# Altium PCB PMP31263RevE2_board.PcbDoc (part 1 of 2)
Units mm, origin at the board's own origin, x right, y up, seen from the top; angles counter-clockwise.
Board outline 111.13 x 148.59 mm, 4 copper layers (Top Layer, Layer 1, Layer 2, Bottom Layer), stack 0.603 mm thick; 138 components, 59 nets, 350 pads, 1544 vias.
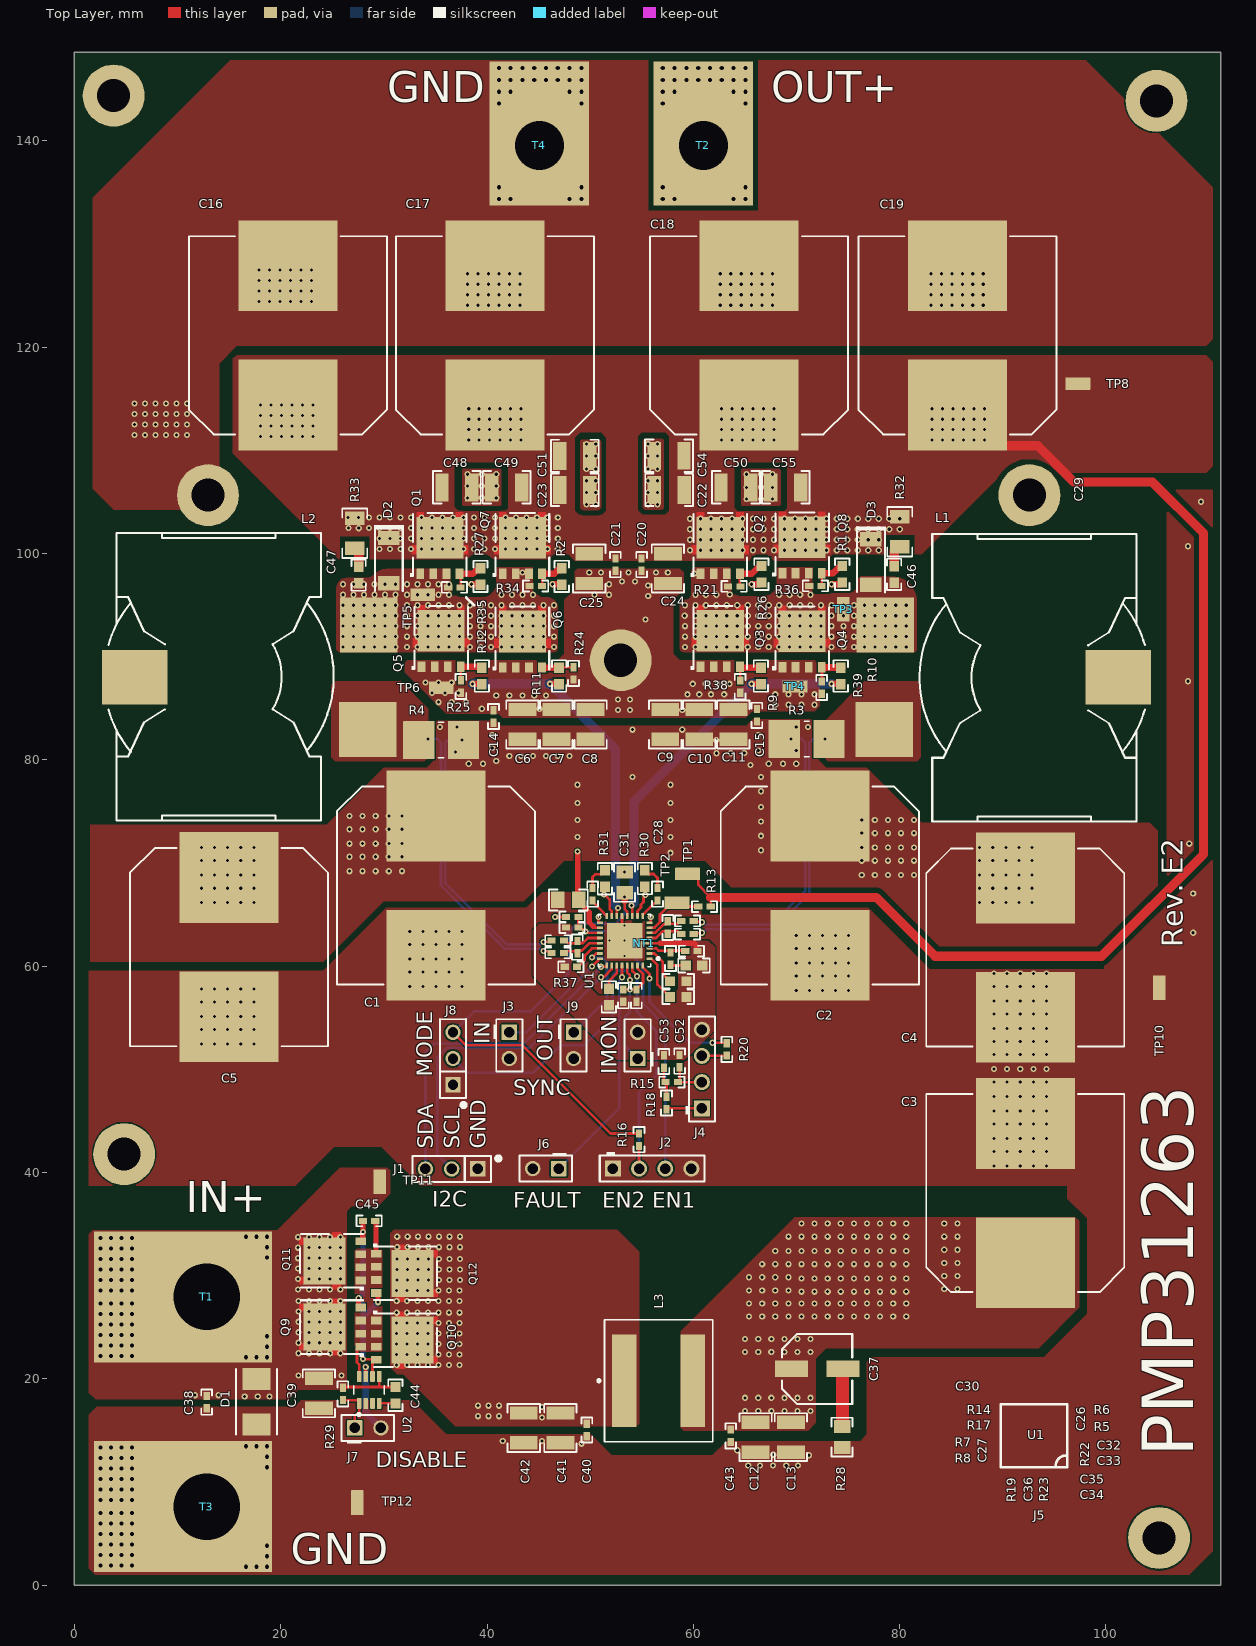
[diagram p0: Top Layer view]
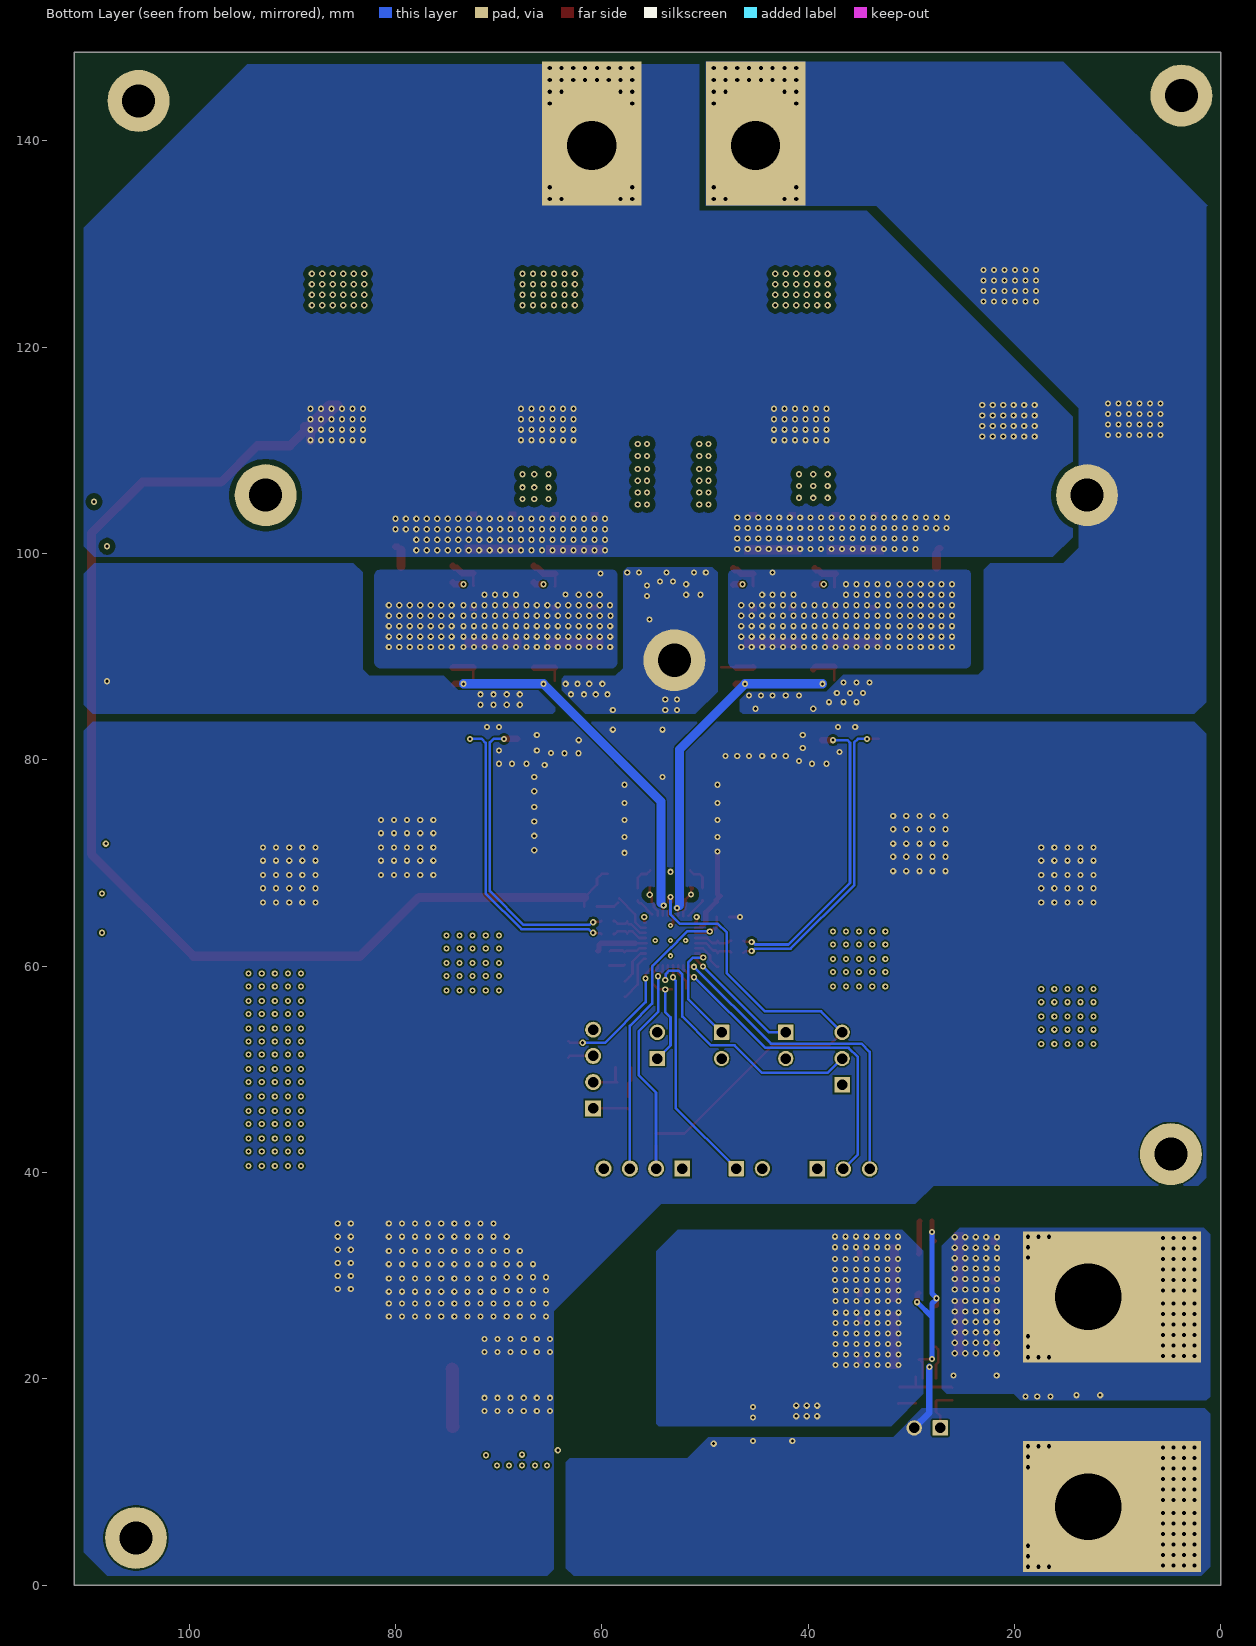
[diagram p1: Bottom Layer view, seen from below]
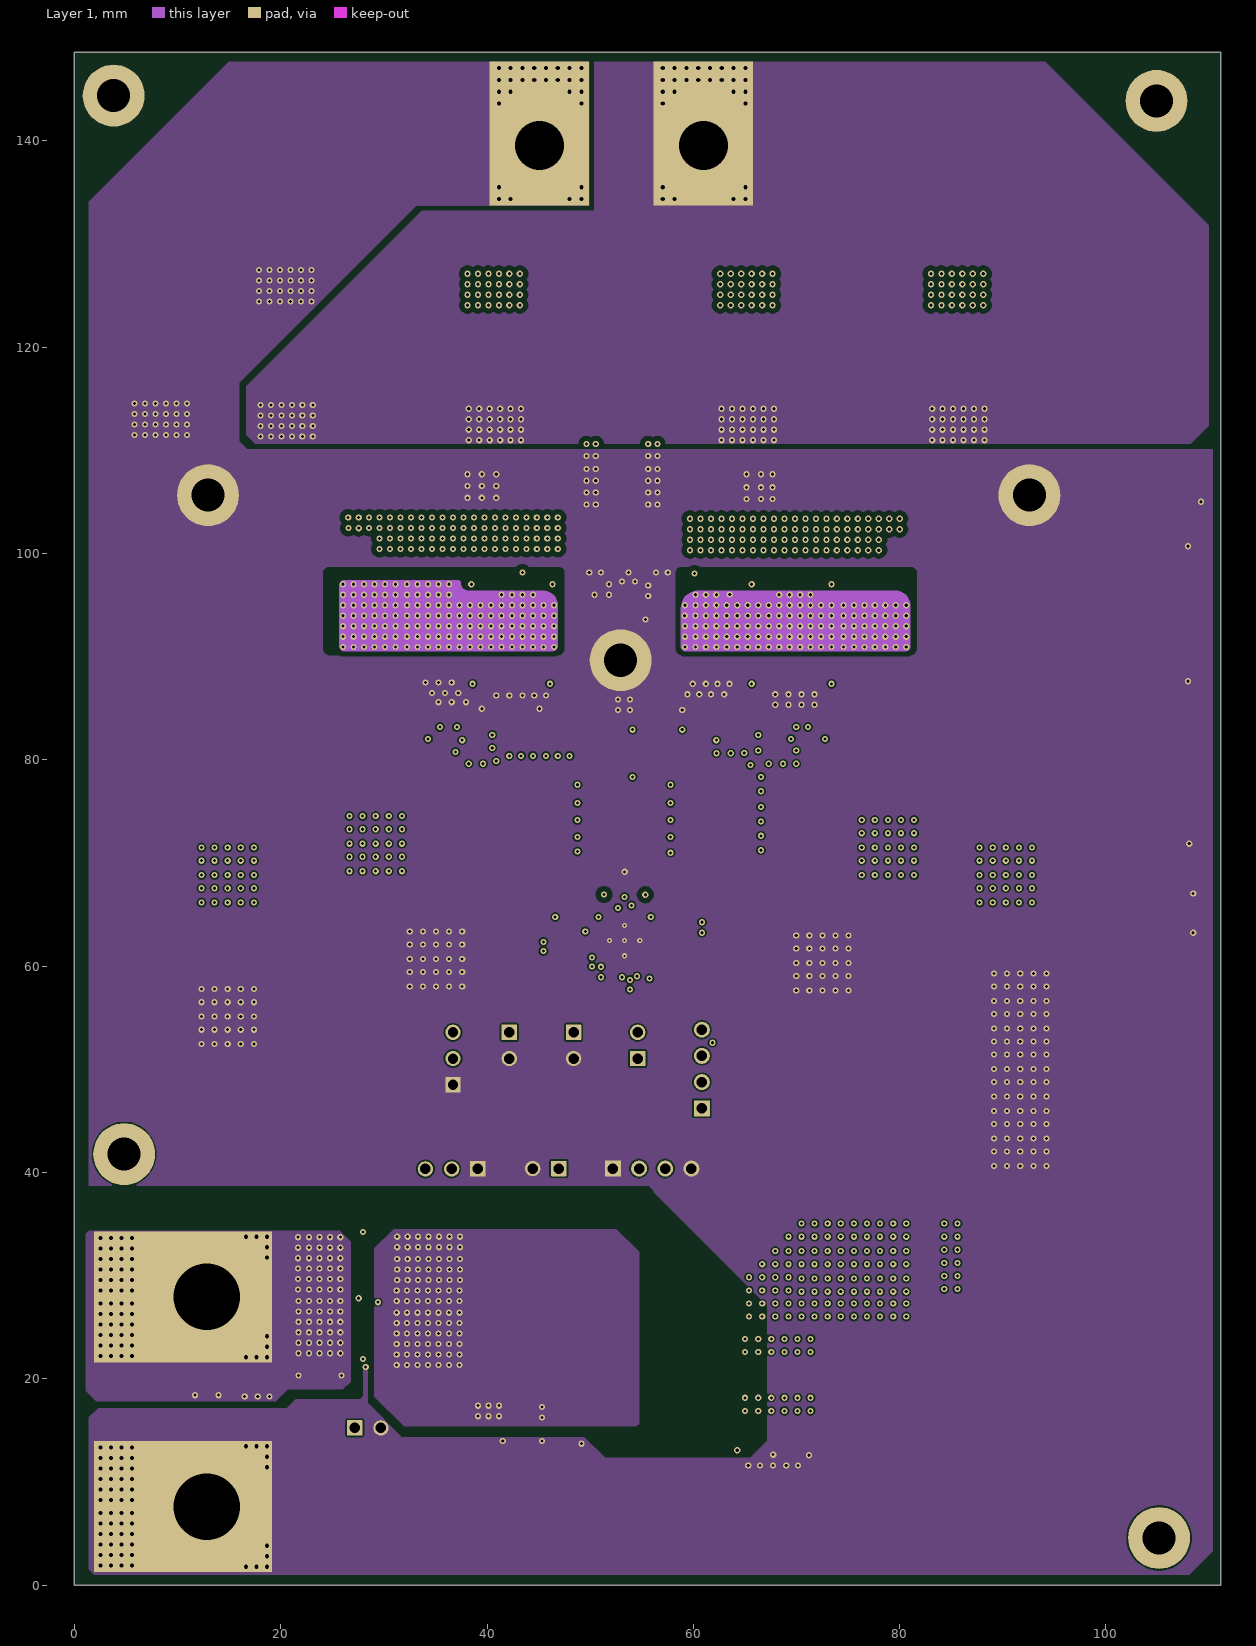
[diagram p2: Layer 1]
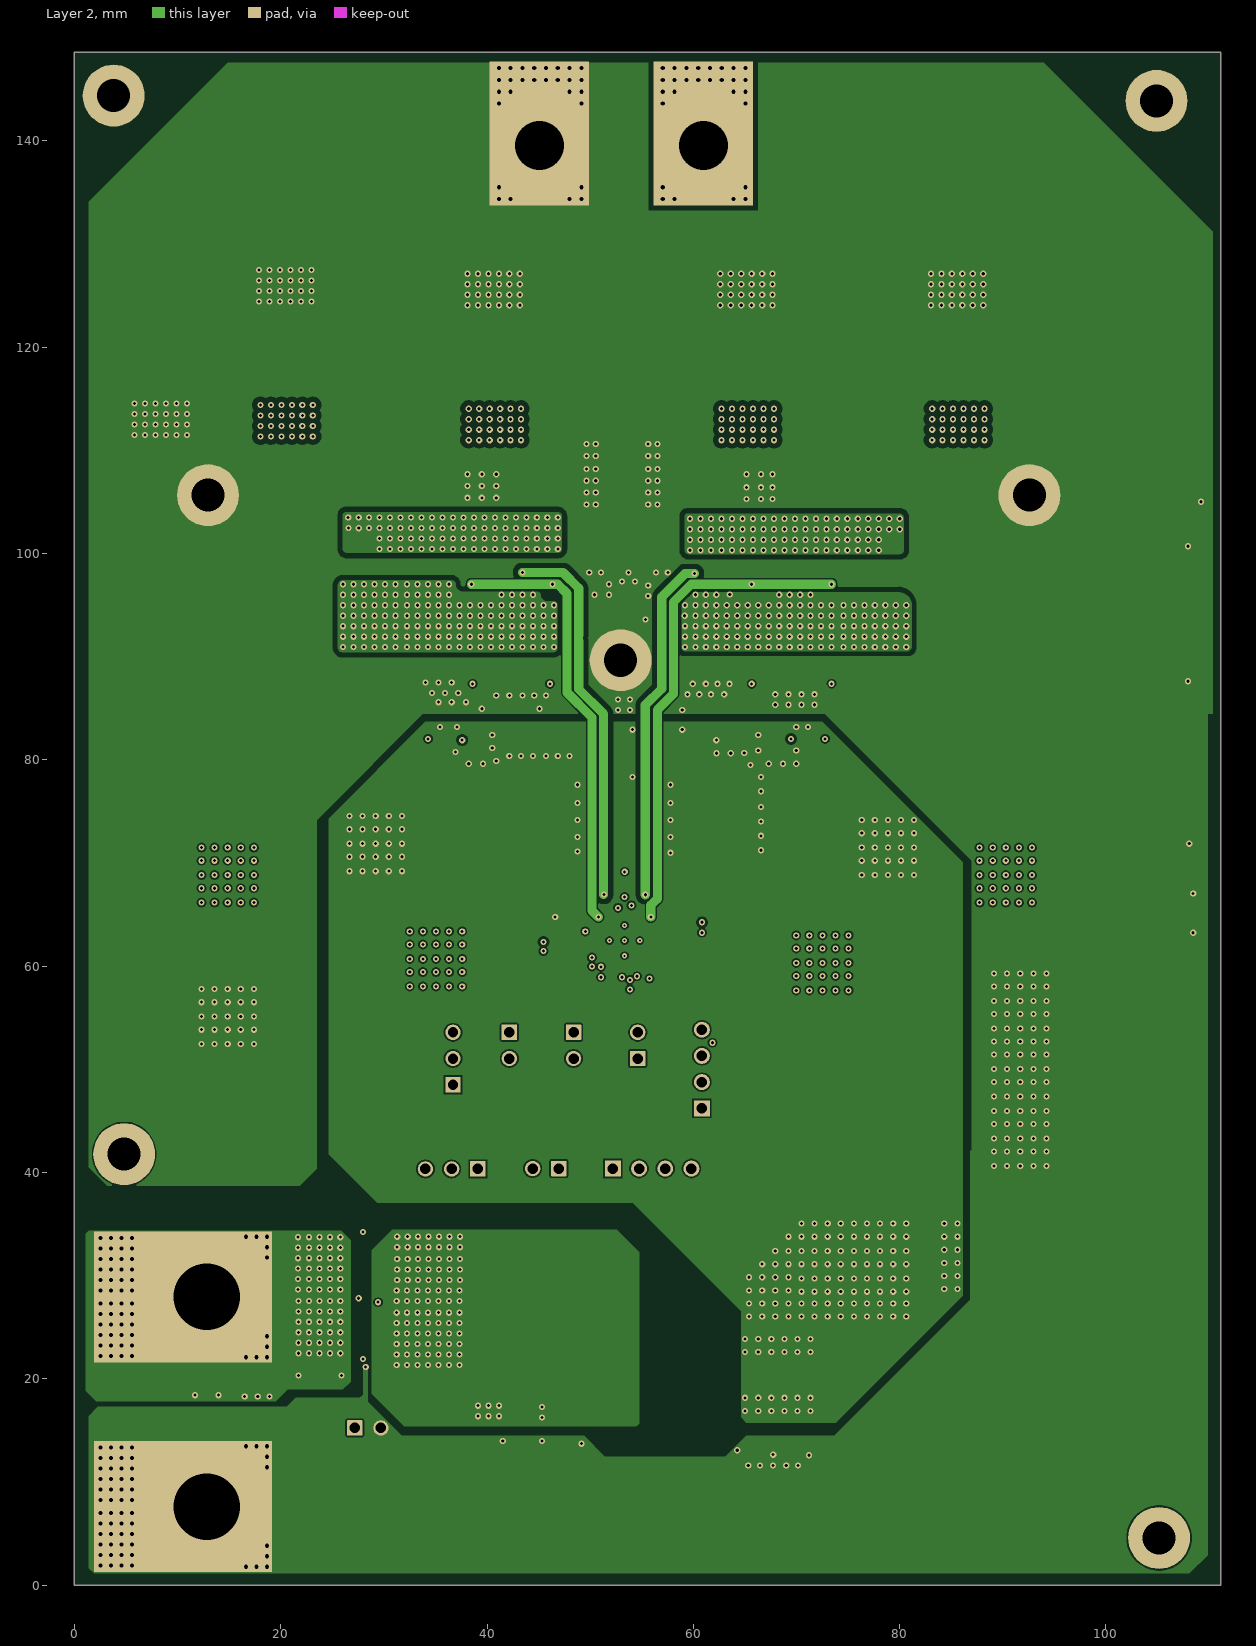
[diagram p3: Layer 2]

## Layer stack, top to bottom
Top Solder: solder mask 0.0102, Solder Resist, Dk 3.5
Top Layer: signal copper 0.0356
Dielectric 2: prepreg 0.0711, PP-006, Dk 4.1
Layer 1: signal copper 0.035
Dielectric 1: dielectric 0.32, FR-4, Dk 4.8
Layer 2: signal copper 0.035
Dielectric 3: prepreg 0.0711, PP-006, Dk 4.1
Bottom Layer: signal copper 0.0356
Bottom Solder: solder mask 0.0102, Solder Resist, Dk 3.5

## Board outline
0,0 0,148.59 111.125,148.59 111.125,0

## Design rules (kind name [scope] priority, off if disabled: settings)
Clearance SW [Not InNet('NetR1_1') And Not InNet('NetR2_2') vs InNet('SW1')  Or  InNet('SW2')  Or  InNet('Vboost')] p1: gap=0.508 ignorepadtopadclearanceinfootprint=FALSE
Clearance Clearance_1 [All] p2: gap=0.152 ignorepadtopadclearanceinfootprint=FALSE
HoleSize [All] p1: absolutevalues=TRUE maxlimit=8 minlimit=0.2 maxpercent=80.000 minpercent=20.000
MinimumAnnularRing [All] p1: minimumring=0.15
MinimumSolderMaskSliver [All] p1: minsoldermaskwidth=0.127
PolygonConnect [All] p1: connectstyle=Direct reliefconductorwidth=0.254 reliefentries=4 polygonreliefangle="90 Angle" airgapwidth=0.254
RoutingVias [All] p1: holewidth=0.3 width=0.6 viastyle="Through Hole" minholewidth=0.3 minwidth=0.6 maxholewidth=0.711 maxwidth=1.27
SolderMaskExpansion [All] p1: expansion=0.102 istentingtop=FALSE
Width [All] p1: maxlimit=1.27 minlimit=0.254 preferedwidth=0.254 minimp=50.000000 maximp=50.000000 favimp=50.000000
28 further rules are at their usual default settings.

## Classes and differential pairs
component class PMP31263RevE2_Input: C37 C38 C39 C40 C41 C42 C43 C44 C45 D1 J7 L3 Q9 Q10 Q11 Q12 R28 R29 T1 T3 TP11 TP12 U2
component class PMP31263: C1 C2 C3 C4 C5 C6 C7 C8 C9 C10 C11 C12 C13 C14 C15 C16 C17 C18 C19 C20 C21 C22 C23 C24 C25 C26 C27 C28 C29 C30 C31 C32 C33 C34 C35 C36 C46 C47 C48 C49 C50 C51 C52 C53 C54 C55 D2 D3 J1 J2 J3 J4 J5 J6 J8 J9 L1 L2 NT1 Q1 Q2 Q3 Q4 Q5 Q6 Q7 Q8 R1 R2 R3 R4 R5 R6 R7 R8 R9 R10 R11 R12 R13 R14 R15 R16 R17 R18 R19 R20 R21 R22 R23 R24 R25 R26 R27 R30 R31 R32 R33 R34 R35 R36 R37 R38 R39 T2 T4 TP1 TP2 TP3 TP4 TP5 TP6 TP8 TP10 U1

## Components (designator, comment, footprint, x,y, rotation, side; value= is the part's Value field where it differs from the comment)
C1 "EMVE500GTR102MMN0S" CAPSMT_62_MN0 35.052,67.818 r270 top value=1000uF
C2 "EMVE500GTR102MMN0S" CAPSMT_62_MN0 72.263,67.818 r270 top value=1000uF
C3 "EMVE500GTR102MMN0S" CAPSMT_62_MN0 92.182,38.013 r90 top value=1000uF
C4 "EMVE500GTR102MMN0S" CAPSMT_62_MN0 92.182,61.811 r270 top value=1000uF
C5 "EMVE500GTR102MMN0S" CAPSMT_62_MN0 14.986,61.849 r270 top value=1000uF
C6 "UMJ325KB7106KMHT" 1210_270 43.434,83.439 r90 top value=10uF
C7 "UMJ325KB7106KMHT" 1210_270 46.736,83.439 r90 top value=10uF
C8 "UMJ325KB7106KMHT" 1210_270 50.038,83.439 r90 top value=10uF
C9 "UMJ325KB7106KMHT" 1210_270 57.277,83.439 r90 top value=10uF
C10 "UMJ325KB7106KMHT" 1210_270 60.579,83.439 r90 top value=10uF
C11 "UMJ325KB7106KMHT" 1210_270 63.881,83.439 r90 top value=10uF
C12 "UMJ325KB7106KMHT" 1210_270 66.04,14.351 r270 top value=10uF
C13 "UMJ325KB7106KMHT" 1210_270 69.469,14.351 r270 top value=10uF
C14 "CGA2B3X7R1H104K050BB" 0402 40.631,84.203 r90 top value=0.1uF
C15 "CGA2B3X7R1H104K050BB" 0402 66.167,84.328 r90 top value=0.1uF
C16 "EMVE500GTR102MMN0S" CAPSMT_62_MN0 20.701,121.158 r90 top value=1000uF
C17 "EMVE500GTR102MMN0S" CAPSMT_62_MN0 40.767,121.158 r90 top value=1000uF
C18 "EMVE500GTR102MMN0S" CAPSMT_62_MN0 65.405,121.158 r90 top value=1000uF
C19 "EMVE500GTR102MMN0S" CAPSMT_62_MN0 85.598,121.158 r90 top value=1000uF
C20 "CGA2B3X7R1H104K050BB" 0402 54.991,98.933 r270 top value=0.1uF
C21 "CGA2B3X7R1H104K050BB" 0402 52.451,98.933 r270 top value=0.1uF
C22 "UMJ325KB7106KMHT" 1210_270 57.658,106.172 r180 top value=10uF
C23 "UMJ325KB7106KMHT" 1210_270 48.514,106.172 r0 top value=10uF
C24 "UMJ325KB7106KMHT" 1210_270 57.531,98.552 r270 top value=10uF
C25 "UMJ325KB7106KMHT" 1210_270 49.911,98.552 r270 top value=10uF
C26 "CGA2B2C0G1H101J050BA" 0402 57.531,63.754 r270 top value=100pF
C27 "CGA2B2C0G1H101J050BA" 0402 48.768,61.849 r90 top value=100pF
C28 "CGA2B3X7R1H104K050BB" 0402 56.526,66.982 r270 top value=0.1uF
C29 "CGA2B3X7R1H104K050BB" 0402 50.231,66.982 r90 top value=0.1uF
C30 "CGA4J3X7R1H225K125AB" 0805_HV 47.879,66.421 r180 top value=2.2uF
C31 "CGA4J3X7R1C475K125AE" 0805_HV 53.333,68.137 r90 top value=4.7uF
C32 "GCM155R71H222KA37D" 0402 59.817,61.468 r0 top value=2200pF
C33 "CGA3E3X7R1H474K080AB" 0603 60.071,60.071 r0 top value=0.47uF
C34 "CGA3E3X7R1H334K080AB" 0603 58.547,57.023 r0 top value=0.33uF
C35 "CGA3E3X7R1H334K080AB" 0603 58.547,58.547 r0 top value=0.33uF
C36 "CGA2B2C0G1H101J050BA" 0402 53.213,57.15 r270 top value=100pF
C37 "EEEFT1H470AP" Panasonic_D 72.009,20.955 r0 top value=47uF
C38 "CGA2B3X7R1H104K050BB" 0402 12.827,17.745 r270 top value=0.1uF
C39 "GCM32ER71H475KA55L" 1210_270 23.698,18.592 r270 top value=4.7uF
C40 "CGA2B3X7R1H104K050BB" 0402 49.678,15.039 r270 top value=0.1uF
C41 "UMJ325KB7106KMHT" 1210_270 47.117,15.24 r270 top value=10uF
C42 "UMJ325KB7106KMHT" 1210_270 43.561,15.24 r270 top value=10uF
C43 "CGA2B3X7R1H104K050BB" 0402 63.627,14.478 r270 top value=0.1uF
C44 "CGA3E3X7R1H474K080AE" 0603 31.115,18.415 r90 top value=0.47uF
C45 "CGA2B3X7R1H104K050BB" 0402 28.575,35.306 r180 top value=0.1uF
C46 "CGA3E2X7R2A152K080AA" 0603 79.472,97.982 r270 top value=1500pF
C47 "CGA3E2X7R2A152K080AA" 0603 27.559,97.917 r270 top value=1500pF
C48 "UMJ325KB7106KMHT" 1210_270 37.084,106.426 r0 top value=10uF
C49 "UMJ325KB7106KMHT" 1210_270 41.91,106.426 r180 top value=10uF
C50 "UMJ325KB7106KMHT" 1210_270 64.135,106.426 r0 top value=10uF
C51 "UMJ325KB7106KMHT" 1210_270 48.514,109.474 r0 top value=10uF
C52 "CGA2B3X7R1H103K050BB" 0402 58.674,50.8 r90 top value=0.01uF
C53 "CGA2B3X7R1H103K050BB" 0402 57.15,50.765 r90 top value=0.01uF
C54 "UMJ325KB7106KMHT" 1210_270 57.648,109.484 r180 top value=10uF
C55 "UMJ325KB7106KMHT" 1210_270 68.961,106.426 r180 top value=10uF
D1 "SMBJ33CA-13-F" SMB-Bi 17.653,17.78 r90 top value=33V
D2 "PMEG6030EVPX" SOD-128 30.48,99.314 r270 top value=60V
D3 "PMEG6030EVPX" SOD-128 77.216,99.187 r270 top value=60V
J1 "PEC03SAAN" CONN_PEC03SAAN 36.572,40.346 r180 top
J2 "PBC04SAAN" Sullins_xxC04SAAN 56.007,40.386 r0 top
J3 "PEC02SAAN" CONN_PEC02SAAN 42.164,52.324 r270 top
J4 "PBC04SAAN" Sullins_xxC04SAAN 60.833,50.038 r90 top
J5 "PEC02SAAN" CONN_PEC02SAAN 54.61,52.324 r90 top
J6 "PEC02SAAN" CONN_PEC02SAAN 45.69,40.386 r180 top
J7 "PEC02SAAN" CONN_PEC02SAAN 28.448,15.24 r0 top
J8 "PEC03SAAN" CONN_PEC03SAAN 36.703,51.054 r90 top
J9 "PEC02SAAN" CONN_PEC02SAAN 48.387,52.324 r270 top
L1 "SER2915H-332KL" SER2915H 92.964,88.011 r0 top value=3.3uH
L2 "SER2915H-332KL" SER2915H 14.097,88.011 r180 top locked value=3.3uH
L3 "XAL1010-451MEB" FP-XAL1010-451MEB_SMD2-MFG 56.642,19.812 r0 top value=0.45uH
NT1 "Net-Tie" Net-Tie_10milWide_30milLong 55.262,62.238 r180 top net-tie
Q1 "NVMYS2D9N04CL" SO-8FL 35.433,100.838 r90 top value=60V
Q2 "NVMYS2D9N04CL" SO-8FL 62.611,100.839 r90 top value=60V
Q3 "NVMYS2D9N04CL" SO-8FL 62.611,91.821 r90 top value=60V
Q4 "NVMYS2D9N04CL" SO-8FL 70.548,91.78 r90 top value=60V
Q5 "NVMYS2D9N04CL" SO-8FL 35.56,91.821 r90 top value=60V
Q6 "NVMYS2D9N04CL" SO-8FL 43.434,91.758 r90 top value=60V
Q7 "NVMYS2D9N04CL" SO-8FL 43.434,100.838 r90 top value=60V
Q8 "NVMYS2D9N04CL" SO-8FL 70.548,100.892 r90 top value=60V
Q9 "NVMFWS0D5N04XM" SO-8FL 24.956,25.019 r180 top value=60V
Q10 "NVMFWS0D5N04XM" SO-8FL 32.068,23.749 r0 top value=60V
Q11 "NVMFWS0D5N04XM" SO-8FL 24.957,31.445 r180 top value=60V
Q12 "NVMFWS0D5N04XM" SO-8FL 32.069,30.226 r0 top value=60V
R1 "PMR03EZPJ000" 0603 74.435,98.005 r90 top value=0
R2 "PMR03EZPJ000" 0603 47.242,97.792 r270 top value=0
R3 "WSLP25121L500FEA" FP-WSLP25121L500FEA_2512-MFG 70.993,82.042 r180 top value=1.5m
R4 "WSLP25121L500FEA" FP-WSLP25121L500FEA_2512-MFG 35.56,81.915 r180 top value=1.5m
R5 "RK73Z1ETTP" 0402 59.436,63.119 r0 top value=0
R6 "RK73Z1ETTP" 0402 59.436,64.389 r0 top value=0
R7 "RK73Z1ETTP" 0402 46.863,62.484 r180 top value=0
R8 "RK73Z1ETTP" 0402 46.862,61.296 r180 top value=0
R9 "PMR03EZPJ000" 0603 66.548,88.138 r90 top value=0
R10 "PMR03EZPJ000" 0603 74.295,88.138 r90 top value=0
R11 "PMR03EZPJ000" 0603 46.99,88.138 r90 top value=0
R12 "PMR03EZPJ000" 0603 39.497,88.138 r90 top value=0
R13 "CRCW040249R9FKED" 0402 61.087,65.786 r0 top value=49.9
R14 "RMCF0402FT100K" 0402 48.26,64.77 r180 top value=100k
R15 "CRCW04021K54FKED" 0402 57.912,48.768 r0 top value=1.54k
R16 "RMCF0402FT100K" 0402 54.737,43.18 r90 top value=100k
R17 "CRCW040214K0FKED" 0402 48.26,63.754 r0 top value=14.0k
R18 "CRCW04021K54FKED" 0402 57.404,46.736 r270 top value=1.54k
R19 "PMR03EZPJ000" 0603 51.816,57.023 r90 top value=0
R20 "CRCW0402100KFKED" 0402 63.246,51.943 r270 top value=100k
R21 "RMCF0402FT100K" 0402 63.964,96.825 r0 top value=100k
R22 "RMCF0402FT10K0" 0402 57.785,60.741 r90 top value=10.0k
R23 "CRCW040220K0FKED" 0402 54.483,57.15 r90 top value=20.0k
R24 "RMCF0402FT100K" 0402 48.387,88.392 r90 top value=100k
R25 "RMCF0402FT100K" 0402 37.465,87.122 r90 top value=100k
R26 "PMR03EZPJ000" 0603 66.603,98.005 r90 top value=0
R27 "PMR03EZPJ000" 0603 39.37,97.79 r270 top value=0
R28 "ERJ-6GEY0R00V" 0805_HV 74.422,14.351 r90 top value=0
R29 "RMCF0402FT100K" 0402 26.035,18.542 r90 top value=100k
R30 "PMR03EZPJ000" 0603 55.298,68.509 r270 top value=0
R31 "PMR03EZPJ000" 0603 51.435,68.491 r90 top value=0
R32 "CRCW1206102RFKEA" 1206 80.01,102.108 r90 top value=102
R33 "CRCW1206102RFKEA" 1206 27.178,101.981 r90 top value=102
R34 "RMCF0402FT100K" 0402 44.723,96.857 r0 top value=100k
R35 "RMCF0402FT100K" 0402 36.838,96.725 r0 top value=100k
R36 "RMCF0402FT100K" 0402 71.831,96.869 r0 top value=100k
R37 "RMCF0402FT100K" 0402 48.133,59.944 r180 top value=100k
R38 "RMCF0402FT100K" 0402 64.543,87.1 r90 top value=100k
R39 "RMCF0402FT100K" 0402 72.445,87.014 r270 top value=100k
T1 "CB70-14-CY" CB70-14-CY 12.827,27.94 r0 top
T2 "CB35-36-CY" CB35-36-CY 60.983,139.573 r270 top
T3 "CB70-14-CY" CB70-14-CY 12.827,7.622 r0 top
T4 "CB35-36-CY" CB35-36-CY 45.085,139.573 r270 top
TP1 "RCU-0C" TE_RCU 59.436,68.961 r0 top
TP2 "RCU-0C" TE_RCU 58.42,66.167 r0 top
TP3 "RCU-0C" TE_RCU 74.549,94.615 r90 top
TP4 "RCU-0C" TE_RCU 69.85,87.122 r180 top
TP5 "RCU-0C" TE_RCU 33.782,96.012 r180 top
TP6 "RCU-0C" TE_RCU 35.56,86.995 r180 top
TP8 "RCU-0C" TE_RCU 97.282,116.459 r180 top
TP10 "RCU-0C" TE_RCU 105.156,57.912 r90 top
TP11 "RCU-0C" TE_RCU 29.591,39.116 r90 top
TP12 "RCU-0C" TE_RCU 27.432,8.001 r90 top
U1 "LM5125-Q1RHB" PCBComponent_1 53.34,62.484 r180 top
U2 "LM74502QDDFQ1" DDF0008A-MFG 28.575,18.923 r90 top

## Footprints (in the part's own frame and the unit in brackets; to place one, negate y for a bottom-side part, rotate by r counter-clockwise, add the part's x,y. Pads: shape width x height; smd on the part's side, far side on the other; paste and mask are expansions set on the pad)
0402 [mm] "0402 from SM-752 data"
  rect 0.8x0.6 smd: 1(-0.6,0) 2(0.6,0)
  silkscreen extent -1.22,-0.52 1.22,0.52, body extent -0.55,-0.3 0.55,0.3, height 0.6
0603 [mm] "0603 from SM-752 data"
  rect 1x0.95 smd: 1(-0.8,0) 2(0.8,0)
  silkscreen extent -1.52,-0.69 1.52,0.69, body extent -0.87,-0.47 0.87,0.47, height 1
0805_HV [mil] "0805 with 30mil clearance between pads"
  rect 50x63 smd: 1(-40,0) 2(40,0)
  silkscreen extent -74,-40 74,40, body extent -43,-29 43,29, height 57
1206 [mm] "1206 from SM-752 data"
  rect 1.3x1.85 smd: 1(-1.45,0) 2(1.45,0)
  silkscreen extent -2.4,-1.21 2.4,1.21, body extent -1.7,-0.9 1.7,0.9, height 1.35
1210_270 [mm] "1210"
  rect 1.3x2.7 smd: 1(-1.45,0) 2(1.45,0)
  silkscreen extent -2.32,-1.57 2.32,1.57, body extent -1.7,-1.35 1.7,1.35, height 2.7
CAPSMT_62_MN0 [mm] "18 x 21.5mm:  Chemi-Con MN0"
  rect 8.8x9.6 smd: 1(-6.75,0) 2(6.75,0)
  silkscreen extent -9.6,-9.6 9.6,9.6, body extent -9.6,-9.6 9.6,9.6, height 22
CB35-36-CY [mil] "Terminal 50A Lug"
  rect 550x380 hole 188 copper offset -45,0 paste-99999: 1(0,0)
  body extent -960,-189 230,191, height 614
CB70-14-CY [mil] "Terminal 90A Lug"
  rect 680x500 hole 254 copper offset -90,0 paste-99999: 1(0,0)
  body extent -1300,-260 250,260, height 714
CONN_PEC02SAAN [mm] "SULLINS"
  rrect7% 1.5x1.5 hole 1.016: 1(-1.27,0)
  round 1.5 hole 1.016: 2(1.27,0)
  silkscreen extent -2.54,-1.52 2.54,1.27, body extent -2.54,-1.27 2.54,1.27, height 8.38
CONN_PEC03SAAN [mm] "SULLINS"
  rect 1.5x1.5 hole 1.016: 1(-2.54,0)
  round 1.5 hole 1.016: 2(0,0) 3(2.54,0)
  silkscreen extent -4.72,-1.27 3.81,1.27, body extent -3.84,-1.3 3.84,1.3, height 8.38
DDF0008A-MFG [mm]
  rrect22% 1.05x0.45 smd paste+0 mask+0: 1(-1.3,0.975) 2(-1.3,0.325) 3(-1.3,-0.325) 4(-1.3,-0.975) 5(1.3,-0.975) 6(1.3,-0.325) 7(1.3,0.325) 8(1.3,0.975)
  silkscreen extent -2.5,-1.48 0.4,1.48, body extent -1.92,-1.73 1.92,1.73, height 0.25
FP-WSLP25121L500FEA_2512-MFG [mm]
  rrect3% 3.05x3.68 smd paste+0 mask+0: 1(-2.16,0) 2(2.16,0)
  silkscreen extent -0.26,-1.72 0.26,1.72, body extent -3.78,-1.94 3.78,1.94, height 0.25
FP-XAL1010-451MEB_SMD2-MFG [mm]
  rrect4% 2.38x9 smd paste+0 mask+0: 1(-3.325,0) 2(3.325,0)
  silkscreen extent -5.92,-5.9 5.25,5.9, body extent -5.35,-6 5.35,6, height 0.25
Net-Tie_10milWide_30milLong [mil] "10mil net tie, no solder mask opening, no solder paste"
  rect 30x10 smd paste-5 mask-5: 1(-15,0) 2(15,0)
Panasonic_D [mm] "SMD, 2-Leads, Dia 6.3mm"
  rect 3.2x1.6 smd: 1(-2.5,0) 2(2.5,0)
  silkscreen extent -3.4,-3.4 3.4,3.4, body extent -3.4,-3.4 3.4,3.4, height 6.11
PCBComponent_1 [mm]
  rrect40% 0.6x0.25 smd paste+0 mask+0: 1(-2.4,1.75) 2(-2.4,1.25) 3(-2.4,0.75) 4(-2.4,0.25) 5(-2.4,-0.25) 6(-2.4,-0.75) 7(-2.4,-1.25) 8(-2.4,-1.75) 17(2.4,-1.75) 18(2.4,-1.25) 19(2.4,-0.75) 20(2.4,-0.25) 21(2.4,0.25) 22(2.4,0.75) 23(2.4,1.25) 24(2.4,1.75)
  rrect40% 0.25x0.6 smd paste+0 mask+0: 9(-1.75,-2.4) 10(-1.25,-2.4) 11(-0.75,-2.4) 12(-0.25,-2.4) 13(0.25,-2.4) 14(0.75,-2.4) 15(1.25,-2.4) 16(1.75,-2.4) 25(1.75,2.4) 26(1.25,2.4) 27(0.75,2.4) 28(0.25,2.4) 29(-0.25,2.4) 30(-0.75,2.4) 31(-1.25,2.4) 32(-1.75,2.4)
  rrect3% 3.45x3.45 smd paste-1000 mask+0: 33(0,0)
  silkscreen extent -3.38,-2.55 2.55,2.55, body extent -2.5,-2.5 2.5,2.5, height 1
SER2915H [mm] "COILCRAFT"
  rect 5.59x5.33 smd: 1(-14.355,5.075) 2(-14.455,-5.075)
  rect 6.35x5.28 smd: 3(8.25,0)
  silkscreen extent -11.04,-14 10.81,13.9, body extent -16.7,-14.05 11.22,13.85, height 15.4
SMB-Bi [mm] "Molded Diode, 2-Leads, Body 5.4x3.6mm, IPC Medium Density, based on OnSemi component dimensions"
  rect 2.159x2.743 smd: 1(-2.21,0) 2(2.21,0)
  silkscreen extent -3.17,-1.99 3.17,1.99, body extent -2.65,-1.85 2.65,1.85, height 2.26
SO-8FL [mm] "ON SEMICONDUCTOR, DFN5 5x6, 1.27P, CASE 488AA"
  rect 1x0.75 smd: 1(-2.795,1.905) 2(-2.795,0.635) 3(-2.795,-0.635) 4(-2.795,-1.905)
  rect 4.055x4.56 smd: 5(0.698,0)
  Top Layer region: 0,-2.775 0,2.775 -0.905,2.775 -0.905,-2.775
  Top Layer region: 3.199,1.529 3.199,2.279 2.654,2.279 2.654,1.529
  Top Layer region: 3.199,-2.281 3.199,-1.531 2.649,-1.531 2.649,-2.281
  silkscreen extent -3.1,-2.6 3.1,2.9, body extent -3.17,-2.67 3.17,2.67, height 1.11
SOD-128 [mm] "SMD, 2-Leads, Body 4x2.7mm, Height 1.1mm"
  rect 1.4x2.1 smd paste-0.1: 1(-2.2,0) 2(2.2,0)
  silkscreen extent -3.45,-1.45 2.95,1.45, body extent -2.5,-1.35 2.5,1.35, height 1.11
Sullins_xxC04SAAN [mm] "Header, 2.54 mm, 4x1, TH"
  rect 1.55x1.55 hole 1.016: 1(-3.81,0)
  round 1.55 hole 1.016: 2(-1.27,0) 3(1.27,0) 4(3.81,0)
  silkscreen extent -5.08,-1.27 5.08,1.6, body extent -5.08,-1.27 5.08,1.27, height 8.38
TE_RCU [mm] "SMD, 1-Leads, Body 1.6x0.8mm"
  rrect8% 2.4x1.2 smd: 1(0,0)
  body extent -0.8,-0.45 0.8,0.45, height 1.15

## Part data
C1 C2 C3 C4 C5 C16 C17 C18 C19: library part CMP-0011290-3, "CAP, AL, 1000 uF, 50 V, +/- 20%, SMD", Cap_Case=MN0, Manufacturer=Chemi-Con, Tolerance_%=20%, Value1=Unknown, Value2=50V, ValueDisplayed=1000uF
C6 C7 C8 C9 C10 C11 C12 C13 C22 C23 C24 C25 C41 C42 C48 C49 C50 C51 C54 C55: library part CMP-0009257-2, "CAP, CERM, 10 uF, 50 V, +/- 10%, X7R, AEC-Q200 Grade 1, 1210", Cap_Case=1210, Manufacturer="Taiyo Yuden", Supplier Part Number 1=587-4279-1-ND, TempCo=X7R, Tolerance_%=10%, Value1=Unknown, Value2=50V, ValueDisplayed=10uF
C14 C15 C20 C21 C28 C29 C38 C40 C43 C45: library part CMP-0006325-2, "CAP, CERM, 0.1 uF, 50 V, +/- 10%, X7R, AEC-Q200 Grade 1, 0402", Cap_Case=0402, Manufacturer=TDK, Supplier Part Number 1=445-6899-1-ND, TempCo=X7R, Tolerance_%=10%, Value1="0.039064 ohm", Value2=50V, ValueDisplayed=0.1uF
C26 C27 C36: library part CMP-0006308-2, "CAP, CERM, 100 pF, 50 V, +/- 5%, C0G/NP0, AEC-Q200 Grade 1, 0402", Cap_Case=0402, Manufacturer=TDK, Supplier Part Number 1=445-5596-1-ND, TempCo=C0G/NP0, Tolerance_%=5%, Value1=Unknown, Value2=50V, ValueDisplayed=100pF
C30: library part CMP-0007977-2, "CAP, CERM, 2.2 uF, 50 V, +/- 10%, X7R, AEC-Q200 Grade 1, 0805", Cap_Case=0805, Manufacturer=TDK, Supplier Part Number 1=445-174216-1-ND, TempCo=X7R, Tolerance_%=10%, Value1="0.003288 ohm", Value2=50V, ValueDisplayed=2.2uF
C31: library part CMP-0080701-1, "CAP, CERM, 4.7 µF, 16 V,+/- 10%, X7R, AEC-Q200 Grade 1, 0805", Cap_Case=0805, Manufacturer=TDK, Supplier Part Number 1=445-8788-1-ND, TempCo=X7R, Tolerance_%=10%, Value2=16V, ValueDisplayed=4.7µF
C32: library part CMP-0006357-2, "CAP, CERM, 2200 pF, 50 V, +/- 10%, X7R, AEC-Q200 Grade 1, 0402", Cap_Case=0402, Manufacturer=MuRata, Supplier Part Number 1=490-4914-1-ND, TempCo=X7R, Tolerance_%=10%, Value1=Unknown, Value2=50V, ValueDisplayed=2200pF
C33: library part CMP-0007096-4, "CAP, CERM, 0.47 uF, 50 V, +/- 10%, X7R, AEC-Q200 Grade 1, 0603", Cap_Case=0603, Manufacturer=TDK, Supplier Part Number 1=810-CGA3E3X7R1H474K080AB, TempCo=X7R, Tolerance_%=10%, Value1="0.01064 ohm", Value2=50V, ValueDisplayed=0.47uF
C34 C35: library part CMP-0007095-4, "CAP, CERM, 0.33 uF, 50 V, +/- 10%, X7R, AEC-Q200 Grade 1, 0603", Cap_Case=0603, Manufacturer=TDK, Supplier Part Number 1=445-174426-1-ND, TempCo=X7R, Tolerance_%=10%, Value1="0.01584 ohm", Value2=50V, ValueDisplayed=0.33uF
C37: library part CMP-0011204-2, "CAP, AL, 47 uF, 50 V, +/- 20%, 0.68 ohm, AEC-Q200 Grade 2, SMD", Cap_Case=6.3x5.8mm, Manufacturer=Panasonic, Supplier Part Number 1=PCE5023CT-ND, Tolerance_%=20%, Value1="0.68 ohm", Value2=50V, ValueDisplayed=47uF
C39: library part CMP-0750153-1, "CAP, CERM, 4.7 µF, 50 V,+/- 10%, X7R, AEC-Q200 Grade 1, 1210", Cap_Case=1210, Manufacturer=MuRata, TempCo=X7R, Tolerance_%=10%, Value2=50V, ValueDisplayed=4.7µF
C44: library part CMP-0007097-4, "CAP, CERM, 0.47 uF, 50 V, +/- 10%, X7R, AEC-Q200 Grade 1, 0603", Cap_Case=0603, Manufacturer=TDK, Supplier Part Number 1=445-172475-1-ND, TempCo=X7R, Tolerance_%=10%, Value1=Unknown, Value2=50V, ValueDisplayed=0.47uF
C46 C47: library part CMP-0007083-4, "CAP, CERM, 1500 pF, 100 V, +/- 10%, X7R, AEC-Q200 Grade 1, 0603", Cap_Case=0603, Manufacturer=TDK, Supplier Part Number 1=445-5807-1-ND, TempCo=X7R, Tolerance_%=10%, Value1="1.35428 ohm", Value2=100V, ValueDisplayed=1500pF
C52 C53: library part CMP-0006324-2, "CAP, CERM, 0.01 uF, 50 V, +/- 10%, X7R, AEC-Q200 Grade 1, 0402", Cap_Case=0402, Manufacturer=TDK, Supplier Part Number 1=445-6893-1-ND, TempCo=X7R, Tolerance_%=10%, Value1="0.333065 ohm", Value2=50V, ValueDisplayed=0.01uF
D1: library part CMP-0005564-3, "Diode, TVS, Bi, 33 V, SMB", Manufacturer="Diodes Inc.", Value1=600W
D2 D3: library part CMP-0077008-3, "Diode, Schottky, 60 V, 3 A, SOD-128", Manufacturer=Nexperia, Value1=3A, Value2=0.475V
J1 J8: library part CMP-0002338-1, "Header, 100mil, 3x1, Tin, TH", Color=Black, Current_A=3A, Manufacturer="Sullins Connector Solutions", Supplier Part Number 1=S1012E-03-ND, Voltage_V=1.8kV
J2 J4: library part CMP-0054583-1, "Header, 2.54 mm, 4x1, Gold, TH", Color=Black, Current_A=3A, Manufacturer="Sullins Connector Solutions", Supplier Part Number 1=S1011E-04-ND, Voltage_V=1.8kV
J3 J5 J6 J7 J9: library part CMP-0002337-1, "Header, 100mil, 2x1, Tin, TH", Color=Black, Current_A=3A, Manufacturer="Sullins Connector Solutions", Supplier Part Number 1=S1012E-02-ND, Voltage_V=1.8kV
L1 L2: library part CMP-0060853-1, "Inductor, Shielded E Core, Ferrite, 3.3 uH, 30 A, 0.00186 ohm, SMD", Manufacturer=Coilcraft, Value1="0.00186 ohm", Value2=30A, ValueDisplayed=3.3uH
L3: library part CMP-0090776-1, "Shielded Power Inductors - XAL1010 0.45uH AEC Q-200 20% 0.72mohm SRF: 66MHz 40A", Manufacturer=Coilcraft, Mouser Part Number=994-XAL1010-451MEB, Operating Temperature Range="to +165°C", Self Resonant Frequency=66MHz, Test Frequency=1MHz, Tolerance_%=20%
NT1: library part CMP-0078142-6, "Single point connection between nets.", Manufacturer=N/A
Q1 Q2 Q3 Q4 Q5 Q6 Q7 Q8 Q9 Q10 Q11 Q12: library part CMP-0750168-1, "MOSFET, N-CH, 60 V, 17 A, AEC-Q101, SO-8FL", Alternate Manufacturer=None, Manufacturer="ON Semiconductor", PartNumber=NVMFS5C670NLWFAFT1G, Value1="0.0088 ohm", Value2="20 nC"
R1 R2 R9 R10 R11 R12 R19 R26 R27 R30 R31: library part CMP-0086358-1, "RES, 0, 0%, 0.25 W, AEC-Q200 Grade 0, 0603", Manufacturer=Rohm, Power_W=250mW, Tolerance_%=0%, Value2=0.25W, Value_Code=0000, ValueDisplayed=0
R3 R4: library part CMP-0093820-1, "1.5 mOhms ±1% 3W Chip Resistor 2512 (6432 Metric) Anti-Sulfur, Automotive AEC-Q200, Current Sense, Moisture Resistant, Pulse Withstanding Metal Element", Digikey Part Number=541-10147-1-ND, Manufacturer="Vishay Dale", Mouser Part Number=71-WSLP25121L500FEA, Operating Temperature Range="-65°C to +170°C", Power_W=3W, TempCo=275ppm/°C, Tolerance_%=1%
R5 R6 R7 R8: library part CMP-0027007-2, "RES, 0, 5%, 0.063 W, AEC-Q200 Grade 0, 0402", Manufacturer="KOA Speer", Power_W=63mW, Supplier Part Number 1=660-RK73Z1ETTP, TempCo=ppm/C, Tolerance_%=5%, Value2=0.063W, Value_Code=0000, ValueDisplayed=0
R13: library part CMP-0026404-2, "RES, 49.9, 1%, 0.063 W, AEC-Q200 Grade 0, 0402", Manufacturer=Vishay-Dale, Power_W=63mW, Supplier Part Number 1=541-49.9LCT-ND, TempCo="100 ppm/C", Tolerance_%=1%, Value2=0.063W, Value_Code=49R9, ValueDisplayed=49.9
R14 R16 R21 R24 R25 R29 R34 R35 R36 R37 R38 R39: library part CMP-0026753-1, "RES, 100 k, 1%, 0.063 W, AEC-Q200 Grade 0, 0402", Manufacturer="Stackpole Electronics Inc", Power_W=63mW, Supplier Part Number 1=RMCF0402FT100KCT-ND, TempCo="100 ppm/C", Tolerance_%=1%, Value2=0.063W, Value_Code=100k
R15 R18: library part CMP-0026089-3, "RES, 1.54 k, 1%, 0.063 W, AEC-Q200 Grade 0, 0402", Manufacturer=Vishay-Dale, Power_W=63mW, Supplier Part Number 1=541-1.54KLCT-ND, TempCo="100 ppm/C", Tolerance_%=1%, Value2=0.063W, Value_Code=1k54, ValueDisplayed=1.54k
R17: library part CMP-0026015-3, "RES, 14.0 k, 1%, 0.063 W, AEC-Q200 Grade 0, 0402", Manufacturer=Vishay-Dale, Power_W=63mW, Supplier Part Number 1=541-14.0KLCT-ND, TempCo="100 ppm/C", Tolerance_%=1%, Value2=0.063W, Value_Code=14k0, ValueDisplayed=14.0k
R20: library part CMP-0025950-3, "RES, 100 k, 1%, 0.063 W, AEC-Q200 Grade 0, 0402", Manufacturer=Vishay-Dale, Power_W=63mW, Supplier Part Number 1=541-100KLCT-ND, TempCo="100 ppm/C", Tolerance_%=1%, Value2=0.063W, Value_Code=100k
R22: library part CMP-0026754-1, "RES, 10.0 k, 1%, 0.063 W, AEC-Q200 Grade 0, 0402", Manufacturer="Stackpole Electronics Inc", Power_W=63mW, Supplier Part Number 1=RMCF0402FT10K0CT-ND, TempCo="100 ppm/C", Tolerance_%=1%, Value2=0.063W, Value_Code=10k0, ValueDisplayed=10.0k
R23: library part CMP-0026162-2, "RES, 20.0 k, 1%, 0.063 W, AEC-Q200 Grade 0, 0402", Manufacturer=Vishay-Dale, Power_W=63mW, Supplier Part Number 1=541-20.0KLCT-ND, TempCo="100 ppm/C", Tolerance_%=1%, Value2=0.063W, Value_Code=20k0, ValueDisplayed=20.0k
R28: library part CMP-0020616-3, "RES, 0, 5%, 0.125 W, AEC-Q200 Grade 0, 0805", Manufacturer=Panasonic, Power_W=125mW, Supplier Part Number 1=P0.0ACT-ND, TempCo="600 ppm/C", Tolerance_%=5%, Value2=0.125W, Value_Code=0000, ValueDisplayed=0
R32 R33: library part CMP-0016572-3, "RES, 102, 1%, 0.25 W, AEC-Q200 Grade 0, 1206", Manufacturer=Vishay-Dale, Power_W=250mW, Supplier Part Number 1=541-102FCT-ND, TempCo="100 ppm/C", Tolerance_%=1%, Value2=0.25W, Value_Code=102R, ValueDisplayed=102
T1 T3: library part CMP-0055443-2, "Terminal 90A Lug", Manufacturer=Panduit, Supplier Part Number 1=CB70-14-CY-ND, Voltage_V=600V
T2 T4: library part CMP-0055442-1, "Terminal 50A Lug", Manufacturer=Panduit, Supplier Part Number 1=CB35-36-CY-ND, Voltage_V=600V
TP1 TP2 TP3 TP4 TP5 TP6 TP8 TP10 TP11 TP12: library part CMP-0067620-1, "PC Test Point, SMT", Manufacturer="TE Connectivity", Supplier Part Number 1=A106145CT-ND
U1: library part LM5125, Alternate Manufacturer=-, Manufacturer="Used in BOM report"
U2: library part CMP-0092660-1, "Reverse Polarity Protection Controller with Over Voltage Protection", Manufacturer="Texas Instruments", Max Supply Voltage=60V, Min Supply Voltage=4V, Nominal Supply Current=60uA, Operating Temperature Range="-40°C to +150°C"

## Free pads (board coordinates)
  round 6 hole 3.2: 2(4.826,41.783) 2(12.954,105.664) 2(52.959,89.662) 2(92.583,105.664) ""(3.81,144.399) ""(104.902,143.891) ""(105.156,4.572)

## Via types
v1: diameter 0.6, hole 0.3, Top Layer to Bottom Layer, tented both sides, 1364 vias
v2: diameter 0.813, hole 0.406, Top Layer to Bottom Layer, 172 vias
v3: diameter 0.5, hole 0.2, Top Layer to Bottom Layer, 5 vias
v4: diameter 0.6/0.6/0.6/0.6 (per signal layer), hole 0.3, Top Layer to Bottom Layer, tented both sides, 2 vias
v5: diameter 0.6, hole 0.3, Top Layer to Bottom Layer, tented top, 1 vias

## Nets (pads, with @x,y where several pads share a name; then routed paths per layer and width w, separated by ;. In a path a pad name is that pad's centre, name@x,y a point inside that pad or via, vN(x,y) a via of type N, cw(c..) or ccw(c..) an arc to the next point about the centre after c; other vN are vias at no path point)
AGND: C32.2 C33.2 C34.2 C35.2 C36.2 C52.2 C53.2 J4.4 J5.2 NT1.1 R17.1 R19.1 R23.1 R37.2 U1.4 | length 5.4
  Top Layer w0.254: NT1.1@55.643,62.238 56.761,62.238
  Top Layer w0.508: 56.761,62.238 59.301,62.238 59.309,62.23 60.119,62.23 60.271,62.078 60.271,61.514 60.317,61.468 C32.2@60.417,61.468
EN2: J2.2 R16.1 U1.30 | length 23.5
  Top Layer w0.254: U1.30@54.09,60.084 54.092,60.082 54.092,59.542 54.539,59.095 v1(54.539,59.025) ; J2.2@54.737,40.386 R16.1@54.737,42.58
  Bottom Layer w0.254: v1(54.539,59.025) 54.539,55.57 56.401,53.708 56.401,49.416 54.737,47.752 J2.2@54.737,40.386
FAULT: J6.1 U1.28 | length 22.2
  Top Layer w0.254: v1(53.086,58.928) 53.088,58.93 53.088,60.082 U1.28@53.09,60.084
  Bottom Layer w0.254: J6.1@46.96,40.386 52.832,46.258 52.832,58.606 53.086,58.86 v1(53.086,58.928)
GND: C1.2 C2.2 C3.2 C4.2 C5.2 C6.2 C7.2 C8.2 C9.2 C10.2 C11.2 C12.2 C13.2 C14.2 C15.2 C16.2 C17.2 C18.2 C19.2 C20.2 C21.2 C22.2 C23.2 C24.2 C25.2 C30.2 C31.2 C38.2 C39.2 C40.2 C41.2 C42.2 C43.2 C48.2 C49.2 C50.2 C51.2 C54.2 C55.2 D1.1 J1.1 J2.1 J2.4 J3.2 J6.2 J7.2 J8.1 J9.2 NT1.2 pad.2@12.954,105.664 pad.2@52.959,89.662 pad.2@92.583,105.664 Q3.1 Q3.2 Q3.3 Q4.1 Q4.2 Q4.3 Q5.1 Q5.2 Q5.3 Q6.1 Q6.2 Q6.3 R24.1 R25.1 R28.1 R38.1 R39.2 T3.1 T4.1 TP4.1 TP6.1 TP10.1 TP12.1 U1.13 U1.33 U2.2 U2.7 | length 8.6
  Top Layer w0.254: U1.13@53.09,64.884 53.09,64.082 53.213,63.959 v3(53.34,63.959)
  Top Layer w0.305: v1(28.237,21.158) 28.243,21.152 28.243,20.23 U2.7@28.25,20.223
  Bottom Layer w0.635: v1(28.237,21.158) 28.237,16.721 J7.2@29.718,15.24
  other v1: 65.323,11.611 66.466,11.611 67.736,11.611 69.006,11.611 70.149,11.611 71.21,12.592 67.743,12.65 64.262,13.081 49.149,13.716 41.529,13.97 45.339,13.97 89.154,40.64 90.424,40.64 91.694,40.64 92.964,40.64 94.234,40.64 89.154,42.037 90.424,42.037 91.694,42.037 92.964,42.037 94.234,42.037 89.154,43.307 90.424,43.307 91.694,43.307 92.964,43.307 94.234,43.307 89.154,44.704 90.424,44.704 91.694,44.704 92.964,44.704 94.234,44.704 89.154,45.974 90.424,45.974 91.694,45.974 92.964,45.974 94.234,45.974 89.154,47.371 90.424,47.371 91.694,47.371 92.964,47.371 94.234,47.371 89.154,48.768 90.424,48.768 91.694,48.768 92.964,48.768 94.234,48.768 89.154,50.038 90.424,50.038 91.694,50.038 92.964,50.038 94.234,50.038 89.154,51.435 90.424,51.435 91.694,51.435 92.964,51.435 94.234,51.435 12.319,52.451 13.589,52.451 14.859,52.451 16.129,52.451 17.399,52.451 89.154,52.705 90.424,52.705 91.694,52.705 92.964,52.705 94.234,52.705 12.319,53.848 13.589,53.848 14.859,53.848 16.129,53.848 17.399,53.848 89.154,53.975 90.424,53.975 91.694,53.975 92.964,53.975 94.234,53.975 12.319,55.118 13.589,55.118 14.859,55.118 16.129,55.118 17.399,55.118 89.154,55.372 90.424,55.372 91.694,55.372 92.964,55.372 94.234,55.372 12.319,56.515 13.589,56.515 14.859,56.515 16.129,56.515 17.399,56.515 89.154,56.642 90.424,56.642 91.694,56.642 92.964,56.642 94.234,56.642 69.977,57.658 71.247,57.658 72.517,57.658 73.787,57.658 75.057,57.658 12.319,57.785 13.589,57.785 14.859,57.785 16.129,57.785 17.399,57.785 32.512,58.039 33.782,58.039 35.052,58.039 36.322,58.039 37.592,58.039 89.154,58.039 90.424,58.039 91.694,58.039 92.964,58.039 94.234,58.039 69.977,59.055 71.247,59.055 72.517,59.055 73.787,59.055 75.057,59.055 89.154,59.309 90.424,59.309 91.694,59.309 92.964,59.309 94.234,59.309 32.512,59.436 33.782,59.436 35.052,59.436 36.322,59.436 37.592,59.436 69.977,60.325 71.247,60.325 72.517,60.325 73.787,60.325 75.057,60.325 32.512,60.706 33.782,60.706 35.052,60.706 36.322,60.706 37.592,60.706 69.977,61.722 71.247,61.722 72.517,61.722 73.787,61.722 75.057,61.722 32.512,62.103 33.782,62.103 35.052,62.103 36.322,62.103 37.592,62.103 69.977,62.992 71.247,62.992 72.517,62.992 73.787,62.992 75.057,62.992 108.458,63.246 32.512,63.373 33.782,63.373 35.052,63.373 36.322,63.373 37.592,63.373 108.458,67.056 53.348,69.153 108.077,71.882 52.705,84.836 53.848,84.836 58.928,84.836 39.497,84.963 45.085,84.963 67.945,85.344 69.215,85.344 70.485,85.344 71.755,85.344 35.306,85.598 36.576,85.598 37.973,85.598 52.705,85.852 53.848,85.852 40.894,86.233 42.164,86.233 43.434,86.233 44.577,86.233 45.72,86.233 59.436,86.36 60.579,86.36 61.722,86.36 62.992,86.36 67.945,86.36 69.215,86.36 70.485,86.36 71.755,86.36 34.671,86.487 35.941,86.487 37.211,86.487 59.944,87.376 61.214,87.376 62.357,87.376 63.5,87.376 34.036,87.503 35.306,87.503 36.576,87.503 107.95,87.63 55.372,93.599 55.626,95.885 50.419,96.012 51.816,96.012 55.626,96.901 51.816,97.028 53.086,97.282 54.356,97.282 49.911,98.171 51.054,98.171 53.721,98.171 56.388,98.171 57.531,98.171 107.95,100.711 49.657,104.775 50.546,104.775 55.626,104.775 56.515,104.775 109.22,105.029 65.151,105.283 66.548,105.283 67.691,105.283 38.1,105.41 39.497,105.41 40.894,105.41 49.657,105.918 50.546,105.918 55.626,105.918 56.515,105.918 65.151,106.426 66.548,106.426 67.691,106.426 38.1,106.553 39.497,106.553 40.894,106.553 49.657,107.061 50.546,107.061 55.626,107.061 56.515,107.061 38.1,107.696 39.497,107.696 40.894,107.696 65.151,107.696 66.548,107.696 67.691,107.696 49.657,108.204 50.546,108.204 55.626,108.204 56.515,108.204 49.657,109.474 50.546,109.474 55.626,109.474 56.515,109.474 49.657,110.617 50.546,110.617 55.626,110.617 56.515,110.617 5.842,111.506 6.858,111.506 7.874,111.506 8.89,111.506 9.906,111.506 10.922,111.506 5.842,112.522 6.858,112.522 7.874,112.522 8.89,112.522 9.906,112.522 10.922,112.522 5.842,113.538 6.858,113.538 7.874,113.538 8.89,113.538 9.906,113.538 10.922,113.538 5.842,114.554 6.858,114.554 7.874,114.554 8.89,114.554 9.906,114.554 10.922,114.554 38.1,124.079 39.116,124.079 40.132,124.079 41.148,124.079 42.164,124.079 43.18,124.079 62.611,124.079 63.627,124.079 64.643,124.079 65.659,124.079 66.675,124.079 67.691,124.079 83.029,124.079 84.045,124.079 85.061,124.079 86.077,124.079 87.093,124.079 88.109,124.079 17.907,124.441 18.923,124.441 19.939,124.441 20.955,124.441 21.971,124.441 22.987,124.441 38.1,125.095 39.116,125.095 40.132,125.095 41.148,125.095 42.164,125.095 43.18,125.095 62.611,125.095 63.627,125.095 64.643,125.095 65.659,125.095 66.675,125.095 67.691,125.095 83.029,125.095 84.045,125.095 85.061,125.095 86.077,125.095 87.093,125.095 88.109,125.095 17.907,125.457 18.923,125.457 19.939,125.457 20.955,125.457 21.971,125.457 22.987,125.457 38.1,126.111 39.116,126.111 40.132,126.111 41.148,126.111 42.164,126.111 43.18,126.111 62.611,126.111 63.627,126.111 64.643,126.111 65.659,126.111 66.675,126.111 67.691,126.111 83.029,126.111 84.045,126.111 85.061,126.111 86.077,126.111 87.093,126.111 88.109,126.111 17.907,126.473 18.923,126.473 19.939,126.473 20.955,126.473 21.971,126.473 22.987,126.473 38.1,127.127 39.116,127.127 40.132,127.127 41.148,127.127 42.164,127.127 43.18,127.127 62.611,127.127 63.627,127.127 64.643,127.127 65.659,127.127 66.675,127.127 67.691,127.127 83.029,127.127 84.045,127.127 85.061,127.127 86.077,127.127 87.093,127.127 88.109,127.127 17.907,127.489 18.923,127.489 19.939,127.489 20.955,127.489 21.971,127.489 22.987,127.489
  other v2: 16.637,1.78 17.653,1.78 18.669,1.78 2.54,1.907 3.556,1.907 4.572,1.907 5.588,1.907 18.669,2.796 2.54,2.923 3.556,2.923 4.572,2.923 5.588,2.923 18.669,3.812 2.54,3.939 3.556,3.939 4.572,3.939 5.588,3.939 2.54,4.955 3.556,4.955 4.572,4.955 5.588,4.955 2.54,5.971 3.556,5.971 4.572,5.971 5.588,5.971 2.54,6.987 3.556,6.987 4.572,6.987 5.588,6.987 2.54,8.257 3.556,8.257 4.572,8.257 5.588,8.257 2.54,9.273 3.556,9.273 4.572,9.273 5.588,9.273 2.54,10.289 3.556,10.289 4.572,10.289 5.588,10.289 2.54,11.305 3.556,11.305 4.572,11.305 5.588,11.305 18.669,11.432 2.54,12.321 3.556,12.321 4.572,12.321 5.588,12.321 18.669,12.448 2.54,13.337 3.556,13.337 4.572,13.337 5.588,13.337 16.637,13.464 17.653,13.464 18.669,13.464 41.148,134.366 42.291,134.366 48.006,134.366 49.149,134.366 41.148,135.509 49.149,135.509 41.148,143.637 49.149,143.637 41.148,144.78 42.291,144.78 48.006,144.78 49.149,144.78 41.148,145.923 42.291,145.923 43.434,145.923 44.577,145.923 45.72,145.923 46.863,145.923 48.006,145.923 49.149,145.923 41.148,147.066 42.291,147.066 43.434,147.066 44.577,147.066 45.72,147.066 46.863,147.066 48.006,147.066 49.149,147.066
  other v3: 53.34,61.009 51.865,62.484 53.34,62.484 54.815,62.484
LM51_VCC: C31.1 J8.3 R16.2 U1.12 | length 49.4
  Top Layer w0.254: J8.3@36.703,53.594 37.973,52.324 43.434,52.324 51.978,43.78 R16.2@54.737,43.78 ; 53.34,66.294 53.34,65.532 53.588,65.284 53.588,64.886 U1.12@53.59,64.884
  Top Layer w0.635: 53.34,66.294 v1(53.34,66.707)
  Bottom Layer w0.254: J8.3@36.703,53.594 38.735,55.626 44.196,55.626 47.879,59.309 47.879,63.246 48.768,64.135 52.451,64.135 53.34,65.024 v1(53.34,66.707)
NetC26_1: C26.1 R6.1 U1.6 | length 3.8
  Top Layer w0.254: U1.6@55.74,63.234 56.309,63.234 57.156,64.081 57.358,64.081 57.531,64.254 C26.1@57.531,64.308 ; C26.1@57.531,64.354 C26.1@57.531,64.308 ; R6.1@58.836,64.389 58.736,64.389 58.482,64.135 57.704,64.135 C26.1@57.531,64.308
NetC26_2: C26.2 R5.1 U1.5 | length 3.7
  Top Layer w0.254: U1.5@55.74,62.734 56.384,62.734 57.023,63.373 57.358,63.373 C26.2@57.531,63.2 ; C26.2@57.531,63.154 C26.2@57.531,63.2 ; R5.1@58.836,63.119 58.736,63.119 58.482,63.373 57.704,63.373 C26.2@57.531,63.2
NetC27_1: C27.1 R8.1 U1.21 | length 4.1
  Top Layer w0.254: R8.1@47.463,61.341 47.59,61.468 48.595,61.468 C27.1@48.768,61.295 ; C27.1@48.768,61.249 C27.1@48.768,61.295 ; U1.21@50.94,62.234 50.938,62.232 49.913,62.232 49.203,61.522 48.941,61.522 48.768,61.349 C27.1@48.768,61.295
NetC27_2: C27.2 R7.1 U1.20 | length 4
  Top Layer w0.254: R7.1@47.463,62.484 47.563,62.484 47.817,62.23 48.595,62.23 C27.2@48.768,62.403 ; C27.2@48.768,62.449 C27.2@48.768,62.403 ; U1.20@50.94,62.734 50.938,62.732 49.778,62.732 49.3,62.254 48.917,62.254 C27.2@48.768,62.403
NetC28_1: C28.1 R30.1 | length 2.5
  Top Layer w0.254: R30.1@55.298,69.309 55.298,69.284 55.646,68.936 56.159,68.936 56.526,68.569 C28.1@56.526,67.582
NetC28_2: C28.2 U1.9 | length 2
  Top Layer w0.254: U1.9@55.092,65.057 55.162,65.057 56.215,66.109 56.353,66.109 56.526,66.282 C28.2@56.526,66.382
NetC29_1: C29.1 U1.16 | length 2.1
  Top Layer w0.254: C29.1@50.231,66.382 50.231,66.282 51.316,65.197 51.316,65.159 U1.16@51.59,64.884
NetC29_2: C29.2 R31.2 | length 2.6
  Top Layer w0.254: C29.2@50.231,67.582 50.231,68.646 50.503,68.918 51.087,68.918 51.435,69.266 R31.2@51.435,69.291
NetC32_1: C32.1 R22.2 U1.3 | length 3.7
  Top Layer w0.254: U1.3@55.74,61.734 55.742,61.732 56.378,61.732 56.603,61.507 57.619,61.507 R22.2@57.785,61.341 57.785,61.354 57.958,61.527 59.158,61.527 C32.1@59.217,61.468
NetC33_1: C33.1 R22.1 | length 1.5
  Top Layer w0.254: R22.1@57.785,60.141 57.855,60.071 C33.1@59.271,60.071
NetC34_1: C34.1 U1.1 | length 4.7
  Top Layer w0.254: U1.1@55.74,60.734 55.911,60.734 56.515,60.13 56.515,58.23 57.722,57.023 C34.1@57.747,57.023
NetC35_1: C35.1 U1.2 | length 3.8
  Top Layer w0.254: U1.2@55.74,61.234 55.742,61.232 56.243,61.232 57.023,60.452 57.023,59.271 57.374,58.92 57.374,58.895 57.722,58.547 C35.1@57.747,58.547
NetC36_1: C36.1 J5.1 R23.2 U1.31 | length 11.5
  Top Layer w0.254: C36.1@53.213,57.75 v1(53.848,57.75) R23.2@54.483,57.75 55.118,58.385 55.118,59.265 54.59,59.793 U1.31@54.59,60.084
  Bottom Layer w0.254: v1(53.848,57.75) 53.848,55.562 53.34,55.054 53.34,52.324 J5.1@54.61,51.054
NetC37_2: C37.2 R28.2 | length 5.6
  Top Layer w1.27: R28.2@74.422,15.367 74.466,15.367 74.466,20.911 C37.2@74.509,20.955
NetC38_1: C38.1 C39.1 C44.2 D1.2 Q9.5 Q11.5 R29.2 T1.1 TP11.1 U2.5 | length 6.1
  Top Layer w0.254: R29.2@26.035,19.142 26.108,19.215 C44.2@31.115,19.215 ; 29.559,19.271 U2.5@29.559,20.214
  other v1: 16.51,18.288 17.78,18.288 18.923,18.288 11.684,18.415 13.97,18.415 21.717,20.32 25.908,20.32 21.717,22.479 22.733,22.479 23.749,22.479 24.765,22.479 25.781,22.479 21.717,23.495 22.733,23.495 23.749,23.495 24.765,23.495 25.781,23.495 21.717,24.511 22.733,24.511 23.749,24.511 24.765,24.511 25.781,24.511 21.717,25.527 22.733,25.527 23.749,25.527 24.765,25.527 25.781,25.527 21.717,26.543 22.733,26.543 23.749,26.543 24.765,26.543 25.781,26.543 21.717,27.559 22.733,27.559 23.749,27.559 24.765,27.559 25.781,27.559 21.692,28.651 22.733,28.651 23.749,28.651 24.765,28.651 25.781,28.651 21.692,29.667 22.733,29.667 23.749,29.667 24.765,29.667 25.781,29.667 21.692,30.683 22.733,30.683 23.749,30.683 24.765,30.683 25.781,30.683 21.692,31.699 22.733,31.699 23.749,31.699 24.765,31.699 25.781,31.699 21.692,32.715 22.733,32.715 23.749,32.715 24.765,32.715 25.781,32.715 21.692,33.731 22.733,33.731 23.749,33.731 24.765,33.731 25.781,33.731
  other v2: 16.637,22.098 17.653,22.098 18.669,22.098 2.54,22.225 3.556,22.225 4.572,22.225 5.588,22.225 18.669,23.114 2.54,23.241 3.556,23.241 4.572,23.241 5.588,23.241 18.669,24.13 2.54,24.257 3.556,24.257 4.572,24.257 5.588,24.257 2.54,25.273 3.556,25.273 4.572,25.273 5.588,25.273 2.54,26.289 3.556,26.289 4.572,26.289 5.588,26.289 2.54,27.305 3.556,27.305 4.572,27.305 5.588,27.305 2.54,28.575 3.556,28.575 4.572,28.575 5.588,28.575 2.54,29.591 3.556,29.591 4.572,29.591 5.588,29.591 2.54,30.607 3.556,30.607 4.572,30.607 5.588,30.607 2.54,31.623 3.556,31.623 4.572,31.623 5.588,31.623 18.669,31.75 2.54,32.639 3.556,32.639 4.572,32.639 5.588,32.639 18.669,32.766 2.54,33.655 3.556,33.655 4.572,33.655 5.588,33.655 16.637,33.782 17.653,33.782 18.669,33.782
NetC40_1: C40.1 C41.1 C42.1 L3.1 Q10.5 Q12.5
  other v1: 45.339,16.256 39.116,16.383 40.132,16.383 41.148,16.383 45.339,17.272 39.116,17.399 40.132,17.399 41.148,17.399 31.242,21.336 32.258,21.336 33.274,21.336 34.29,21.336 35.306,21.336 36.322,21.336 37.338,21.336 31.242,22.352 32.258,22.352 33.274,22.352 34.29,22.352 35.306,22.352 36.322,22.352 37.338,22.352 31.242,23.368 32.258,23.368 33.274,23.368 34.29,23.368 35.306,23.368 36.322,23.368 37.338,23.368 31.242,24.384 32.258,24.384 33.274,24.384 34.29,24.384 35.306,24.384 36.322,24.384 37.338,24.384 31.242,25.4 32.258,25.4 33.274,25.4 34.29,25.4 35.306,25.4 36.322,25.4 37.338,25.4 31.242,26.416 32.258,26.416 33.274,26.416 34.29,26.416 35.306,26.416 36.322,26.416 37.338,26.416 31.242,27.559 32.258,27.559 33.274,27.559 34.29,27.559 35.306,27.559 36.322,27.559 37.338,27.559 31.242,28.575 32.258,28.575 33.274,28.575 34.29,28.575 35.306,28.575 36.322,28.575 37.338,28.575 31.293,29.591 32.309,29.591 33.325,29.591 34.341,29.591 35.357,29.591 36.373,29.591 37.389,29.591 31.293,30.607 32.309,30.607 33.325,30.607 34.341,30.607 35.357,30.607 36.373,30.607 37.389,30.607 31.293,31.623 32.309,31.623 33.325,31.623 34.341,31.623 35.357,31.623 36.373,31.623 37.389,31.623 31.293,32.766 32.309,32.766 33.325,32.766 34.341,32.766 35.357,32.766 36.373,32.766 37.389,32.766 31.293,33.782 32.309,33.782 33.325,33.782 34.341,33.782 35.357,33.782 36.373,33.782 37.389,33.782
NetC44_1: C44.1 U2.4 | length 1.7
  Top Layer w0.254: U2.4@29.55,17.623 31.234,17.623 C44.1@31.242,17.615
NetC45_1: C45.1 Q9.1 Q9.2 Q9.3 Q10.1 Q10.2 Q10.3 Q11.1 Q11.2 Q11.3 Q12.1 Q12.2 Q12.3 U2.8 | length 6.6
  Top Layer w0.254: U2.8@27.6,20.066 U2.8@27.6,20.223 27.6,21.387 27.396,21.592 27.396,22.866 27.644,23.114 Q9.1@27.751,23.114
  Top Layer w0.5: C45.1@29.175,35.306 29.224,35.257 29.224,32.18 Q12.1@29.274,32.131
NetC45_2: C45.2 Q9.4 Q10.4 Q11.4 Q12.4 U2.6 | length 22.1
  Top Layer w0.254: Q9.4@27.559,27.116 Q9.4@27.751,26.924 ; v1(27.975,21.936) 28.021,21.89 29.227,21.89 Q10.4@29.273,21.844 29.148,21.844 28.9,21.596 U2.6@28.9,20.223 U2.6@28.9,20.066
  Top Layer w0.5: Q9.4@27.559,27.116 v1(27.559,27.813) ; Q11.4@27.751,33.35 27.831,33.35 27.956,33.475 27.956,34.22 v1(27.975,34.239) C45.2@27.975,35.306 ; Q12.4@29.274,28.321 29.294,28.321 29.419,28.196 29.419,27.451 v1(29.439,27.432)
  Bottom Layer w0.254: v1@27.559,27.719 v1(27.559,27.813)
  Bottom Layer w0.5: v1@27.559,27.719 27.975,27.303 27.975,25.984 ; v1(27.559,27.813) 27.559,27.84 27.991,28.272 27.991,34.223 v1(27.975,34.239) ; v1(27.975,21.936) 27.975,25.984 ; v1(29.439,27.432) 29.423,27.432 27.975,25.984
NetC46_1: C46.1 R32.1 | length 2.2
  Top Layer w0.635: R32.1@79.472,100.325 79.804,100.658 R32.1@80.01,100.658
  Top Layer w0.889: C46.1@79.472,98.782 R32.1@79.472,100.325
